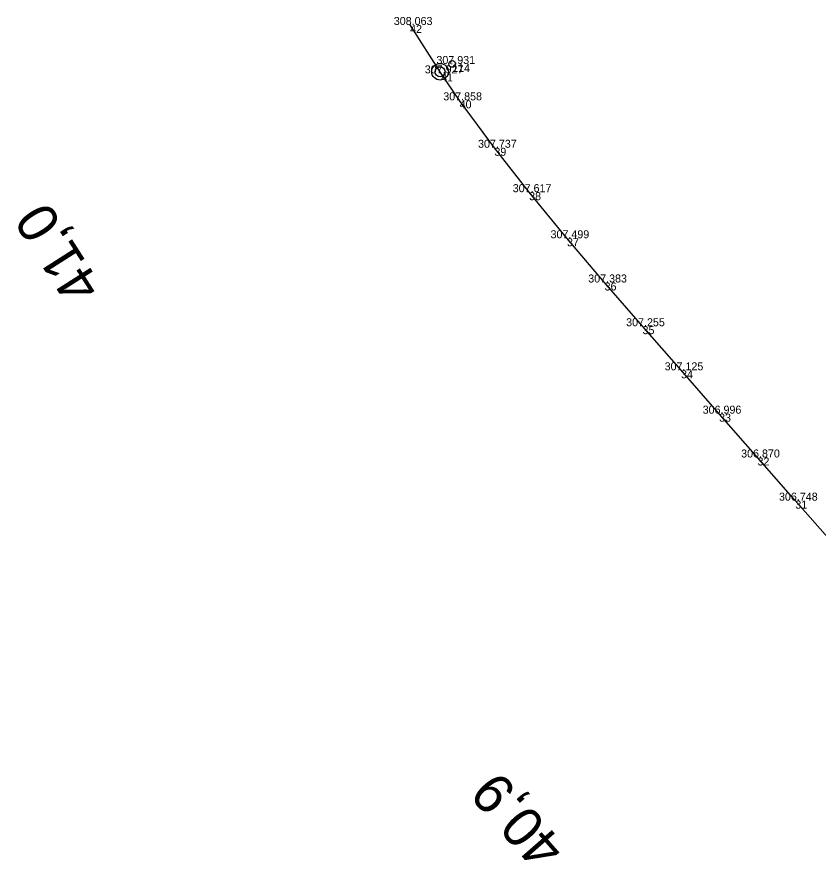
# Model space of a CAD drawing. Extents: x -684938 to -684389, y -1007777 to -1006471.
# Drawn here: x -684937.8 to -684817.7, y -1006597.5 to -1006471 of the extents above; entities that cross this region are included whole.
import ezdxf

# ---------------------------------------------------------------- set-up
doc = ezdxf.new("R2010")
doc.units = 0
for name, color, linetype in [('Vrstva 1', 7, 'Continuous'), ('Vrstva 60', 7, 'Continuous'), ('Vrstva 61', 7, 'Continuous'), ('Vrstva 7', 7, 'Continuous')]:
    doc.layers.add(name, color=color, linetype=linetype)

msp = doc.modelspace()

# ---------------------------------------------------------------- linework, layer by layer
at = {"layer": 'Vrstva 1'}
msp.add_lwpolyline([(-684815.15, -1006550.36), (-684821.1, -1006543.57), (-684826.77, -1006537.1), (-684832.53, -1006530.53), (-684838.23, -1006524.03), (-684844, -1006517.42), (-684849.69, -1006510.86), (-684855.33, -1006504.23), (-684861, -1006497.32), (-684866.21, -1006490.66), (-684871.42, -1006483.55), (-684874.2, -1006479.51), (-684878.84, -1006472.25)], dxfattribs=at)
at = {"layer": 'Vrstva 60'}
for p, q in [((-684878.84, -1006472.25), (-684878.84, -1006472.25)), ((-684872.54, -1006478.1), (-684872.54, -1006478.1)), ((-684874.2, -1006479.51), (-684874.2, -1006479.51)), ((-684871.42, -1006483.55), (-684871.42, -1006483.55)), ((-684866.21, -1006490.66), (-684866.21, -1006490.66)), ((-684861, -1006497.32), (-684861, -1006497.32)), ((-684855.33, -1006504.23), (-684855.33, -1006504.23)), ((-684849.69, -1006510.86), (-684849.69, -1006510.86)), ((-684844, -1006517.42), (-684844, -1006517.42)), ((-684838.23, -1006524.03), (-684838.23, -1006524.03)), ((-684832.53, -1006530.53), (-684832.53, -1006530.53)), ((-684826.77, -1006537.1), (-684826.77, -1006537.1)), ((-684821.1, -1006543.57), (-684821.1, -1006543.57))]:
    msp.add_line(p, q, dxfattribs=at)
at = {"layer": 'Vrstva 7'}
msp.add_line((-684872.52, -1006478.14), (-684872.57, -1006478.06), dxfattribs=at)
for centre, radius in [((-684874.36, -1006479.26), 1.25), ((-684872.54, -1006478.1), 0.5), ((-684874.36, -1006479.26), 0.752)]:
    msp.add_circle(centre, radius, dxfattribs=at)

# ---------------------------------------------------------------- texts
at = {"layer": 'Vrstva 60'}
for s, p in [('42', (-684878.84, -1006473.45)), ('114', (-684872.54, -1006479.3)), ('41', (-684874.2, -1006480.71)), ('40', (-684871.42, -1006484.75)), ('39', (-684866.21, -1006491.86)), ('38', (-684861, -1006498.52)), ('37', (-684855.33, -1006505.43)), ('36', (-684849.69, -1006512.06)), ('35', (-684844, -1006518.61)), ('34', (-684838.23, -1006525.23)), ('33', (-684832.53, -1006531.73)), ('32', (-684826.77, -1006538.3)), ('31', (-684821.1, -1006544.77))]:
    msp.add_text(s, height=1.2, dxfattribs=at).set_placement(p)
at = {"layer": 'Vrstva 61'}
for s, p in [('308.063', (-684881.29, -1006472.25)), ('307.931', (-684874.9, -1006478.1)), ('307.927', (-684876.65, -1006479.51)), ('307.858', (-684873.87, -1006483.55)), ('307.737', (-684868.66, -1006490.66)), ('307.617', (-684863.46, -1006497.32)), ('307.499', (-684857.79, -1006504.23)), ('307.383', (-684852.14, -1006510.86)), ('307.255', (-684846.46, -1006517.42)), ('307.125', (-684840.69, -1006524.03)), ('306.996', (-684834.99, -1006530.53)), ('306.870', (-684829.22, -1006537.1)), ('306.748', (-684823.55, -1006543.57))]:
    msp.add_text(s, height=1.2, dxfattribs=at).set_placement(p)
at = {"layer": 'Vrstva 7'}
for s, rotation, p in [('41,0', 122.5798, (-684924.92, -1006511.57)), ('40,9', 131.1959, (-684855.32, -1006595.56))]:
    msp.add_text(s, height=6, rotation=rotation, dxfattribs=at).set_placement(p)

doc.saveas('drawing.dxf')
